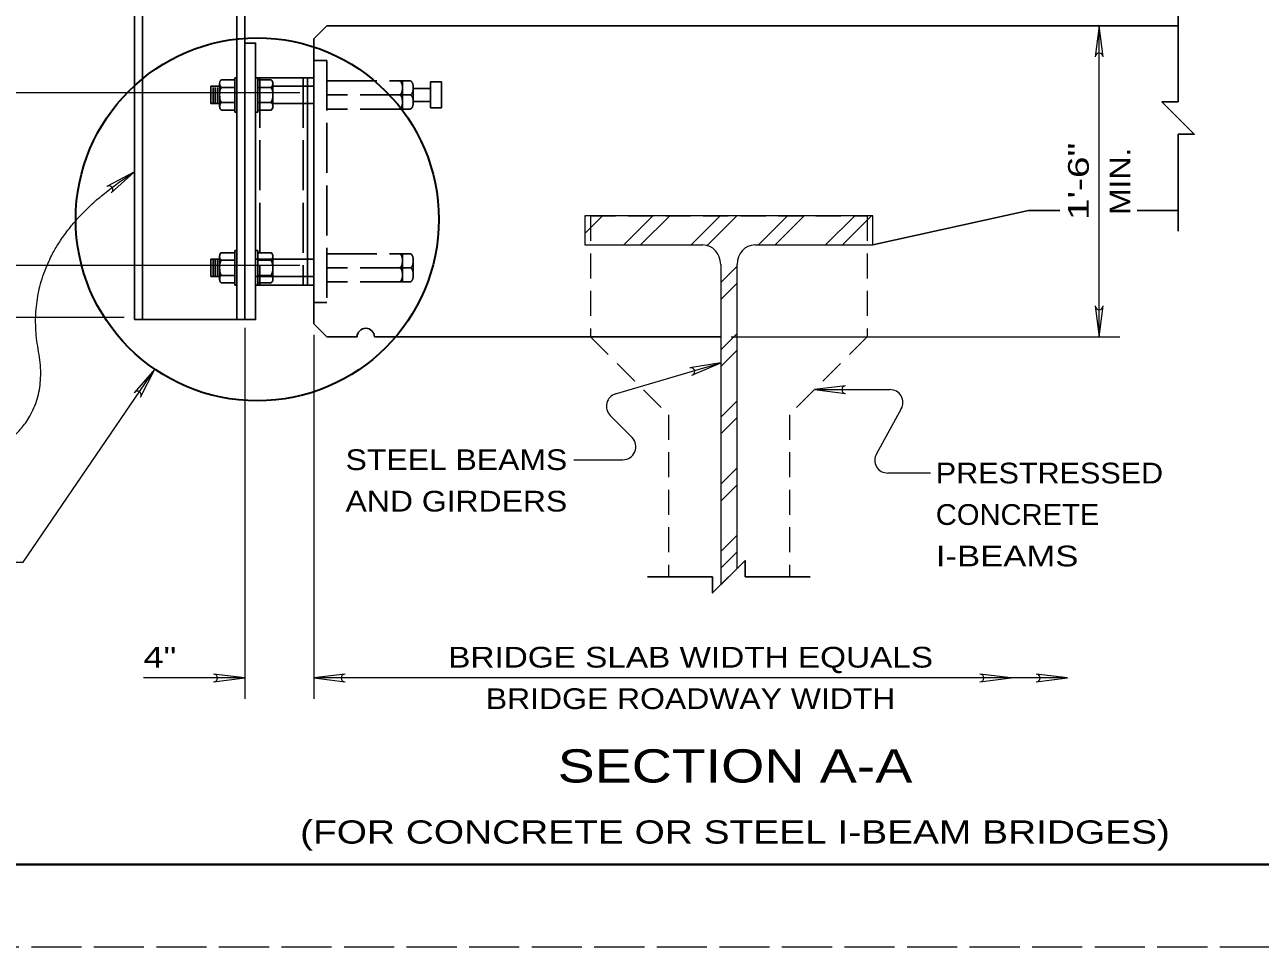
# Model space of a CAD drawing. Extents: x 1285 to 1427, y 1365 to 1427.
# Drawn here: x 1405.11 to 1415.03, y 1397.33 to 1404.75 of the extents above; entities that cross this region are included whole.
import ezdxf
from ezdxf.enums import TextEntityAlignment as Align

# ---------------------------------------------------------------- set-up
doc = ezdxf.new("R2010")
doc.units = 0
doc.header["$LTSCALE"] = 0.067
doc.linetypes.add('LONG_DASHED', pattern=[7.5, 6, -1.5])
doc.linetypes.add('MEDIUM_DASHED', pattern=[4.5, 3, -1.5])
for name, color, linetype, lineweight in [('1', 7, 'Continuous', 40), ('42', 7, 'Continuous', 25), ('43', 7, 'Continuous', 25), ('44', 7, 'Continuous', 13)]:
    doc.layers.add(name, color=color, linetype=linetype, lineweight=lineweight)

msp = doc.modelspace()

# ---------------------------------------------------------------- linework, layer by layer
at = {"layer": '1', "linetype": 'LONG_DASHED', "lineweight": 13}
msp.add_lwpolyline([(1381.33333, 1426.66667), (1426.66667, 1426.66667), (1426.66667, 1397.33333), (1381.33333, 1397.33333)], close=True, dxfattribs=at)
at = {"layer": '1'}
msp.add_lwpolyline([(1384, 1426), (1426, 1426), (1426, 1398), (1384, 1398)], close=True, dxfattribs=at)
at = {"layer": '42'}
for p, q in [((1405.98811, 1409.04422), (1405.98811, 1402.37744)), ((1406.05133, 1409.04422), (1406.05133, 1402.37744)), ((1406.811, 1409.04422), (1406.811, 1402.37744)), ((1414.37189, 1404.90533), (1414.37189, 1404.12733)), ((1407.42967, 1404.63444), (1407.53389, 1404.73867)), ((1407.53389, 1404.73867), (1414.37189, 1404.73867)), ((1407.42967, 1404.63444), (1407.42967, 1402.34289)), ((1406.67222, 1404.09178), (1406.67222, 1404.27411)), ((1406.68956, 1404.30444), (1406.79378, 1404.30444)), ((1406.79378, 1404.32178), (1406.79367, 1404.04411)), ((1406.79378, 1404.32178), (1406.811, 1404.32178)), ((1407.42978, 1404.32189), (1406.96111, 1404.32189)), ((1406.97833, 1404.32178), (1406.96111, 1404.32178)), ((1406.97833, 1404.32178), (1406.97844, 1404.04411)), ((1407.08256, 1404.30444), (1406.97833, 1404.30444)), ((1407.09989, 1404.09178), (1407.09989, 1404.27411)), ((1407.37778, 1404.25233), (1407.37778, 1404.32189)), ((1406.62011, 1404.24367), (1406.62011, 1404.12211)), ((1406.63744, 1404.24367), (1406.63744, 1404.12211)), ((1406.65478, 1404.24367), (1406.65478, 1404.12211)), ((1406.79367, 1404.24367), (1406.68956, 1404.24367)), ((1406.97844, 1404.24367), (1407.08256, 1404.24367)), ((1407.09989, 1404.25233), (1407.42978, 1404.25233)), ((1406.79367, 1404.12211), (1406.68956, 1404.12211)), ((1406.97844, 1404.12211), (1407.08256, 1404.12211)), ((1407.09989, 1404.11344), (1407.42967, 1404.11344)), ((1407.37778, 1402.86344), (1407.37778, 1404.11344)), ((1406.79367, 1404.06144), (1406.68956, 1404.06144)), ((1406.79367, 1404.04411), (1406.811, 1404.04411)), ((1406.97844, 1404.04411), (1406.96111, 1404.04411)), ((1406.97844, 1404.06144), (1407.08256, 1404.06144)), ((1414.37189, 1403.86678), (1414.37189, 1403.08867)), ((1411.91956, 1402.97756), (1413.16956, 1403.25533)), ((1413.16956, 1403.25533), (1413.42056, 1403.25533)), ((1414.04189, 1403.25533), (1414.37189, 1403.25533)), ((1406.67222, 1402.70289), (1406.67222, 1402.88522)), ((1406.68956, 1402.91556), (1406.79378, 1402.91556)), ((1406.79378, 1402.93289), (1406.79367, 1402.65522)), ((1406.79378, 1402.93289), (1406.811, 1402.93289)), ((1406.97833, 1402.93289), (1406.96111, 1402.93289)), ((1406.97833, 1402.93289), (1406.97844, 1402.65522)), ((1407.08256, 1402.91556), (1406.97833, 1402.91556)), ((1407.09989, 1402.70289), (1407.09989, 1402.88522)), ((1406.62011, 1402.85478), (1406.62011, 1402.73322)), ((1406.63744, 1402.85478), (1406.63744, 1402.73322)), ((1406.65478, 1402.85478), (1406.65478, 1402.73322)), ((1406.79367, 1402.85478), (1406.68956, 1402.85478)), ((1406.97844, 1402.85478), (1407.08256, 1402.85478)), ((1407.09989, 1402.86344), (1407.42967, 1402.86344)), ((1406.79367, 1402.73322), (1406.68956, 1402.73322)), ((1406.97844, 1402.73322), (1407.08256, 1402.73322)), ((1407.09989, 1402.72456), (1407.42967, 1402.72456)), ((1407.37778, 1402.65522), (1407.37778, 1402.72456)), ((1406.79367, 1402.67256), (1406.68956, 1402.67256)), ((1406.79367, 1402.65522), (1406.811, 1402.65522)), ((1406.97844, 1402.65522), (1406.96111, 1402.65522)), ((1406.97844, 1402.67256), (1407.08256, 1402.67256)), ((1407.42967, 1402.34289), (1407.53389, 1402.23867)), ((1407.53389, 1402.23867), (1407.77689, 1402.23867)), ((1407.91578, 1402.23867), (1410.69733, 1402.23867)), ((1410.11022, 1400.31133), (1410.63267, 1400.31133)), ((1410.89322, 1400.31133), (1411.41578, 1400.31133))]:
    msp.add_line(p, q, dxfattribs=at)
at = {"layer": '42', "linetype": 'LONG_DASHED'}
for p, q in [((1406.99589, 1404.32189), (1406.99589, 1402.65522)), ((1407.343, 1404.32189), (1407.343, 1402.65522)), ((1407.53378, 1404.29589), (1408.20222, 1404.29589)), ((1408.14144, 1404.29589), (1408.14144, 1404.23522)), ((1408.45389, 1404.28733), (1408.36711, 1404.28733)), ((1408.36711, 1404.28733), (1408.36711, 1404.079)), ((1407.37778, 1404.25233), (1407.37778, 1404.11344)), ((1408.20222, 1404.183), (1407.53378, 1404.183)), ((1408.22822, 1404.23522), (1408.36711, 1404.23522)), ((1408.22822, 1404.23522), (1408.22822, 1404.15211)), ((1408.22822, 1404.131), (1408.36711, 1404.131)), ((1408.20222, 1404.07011), (1407.53378, 1404.07011)), ((1407.53378, 1402.907), (1408.20222, 1402.907)), ((1408.14144, 1402.907), (1408.14144, 1402.84633)), ((1406.96111, 1402.86344), (1407.09989, 1402.86344)), ((1407.37778, 1402.86344), (1407.37778, 1402.72456)), ((1408.20222, 1402.79411), (1407.53378, 1402.79411)), ((1408.22822, 1402.84633), (1408.22822, 1402.76322)), ((1406.96111, 1402.72456), (1407.09989, 1402.72456)), ((1408.20222, 1402.68122), (1407.53378, 1402.68122))]:
    msp.add_line(p, q, dxfattribs=at)
at = {"layer": '42', "lineweight": 13}
for p, q in [((1409.60644, 1403.20456), (1409.61278, 1403.21089)), ((1409.60644, 1403.07), (1409.74733, 1403.21089)), ((1409.91967, 1402.97756), (1410.153, 1403.21089)), ((1410.05422, 1402.97756), (1410.28756, 1403.21089)), ((1410.45989, 1402.97756), (1410.69322, 1403.21089)), ((1410.58656, 1402.96967), (1410.82778, 1403.21089)), ((1411.00011, 1402.97756), (1411.23344, 1403.21089)), ((1411.13467, 1402.97756), (1411.368, 1403.21089)), ((1411.54033, 1402.97756), (1411.77367, 1403.21089)), ((1411.67489, 1402.97756), (1411.90822, 1403.21089)), ((1409.60644, 1402.97756), (1410.55456, 1402.97756)), ((1410.69733, 1402.67478), (1410.82867, 1402.80611)), ((1410.69733, 1402.54022), (1410.82867, 1402.67156)), ((1410.69733, 1402.13456), (1410.82867, 1402.26589)), ((1410.69733, 1402), (1410.82867, 1402.13133)), ((1410.69733, 1401.59433), (1410.82867, 1401.72567)), ((1410.69733, 1401.45978), (1410.82867, 1401.59111)), ((1410.69733, 1401.05411), (1410.82867, 1401.18544)), ((1410.69733, 1400.91956), (1410.82867, 1401.05089)), ((1410.69733, 1400.51389), (1410.82867, 1400.64522)), ((1410.69733, 1400.37933), (1410.82867, 1400.51067))]:
    msp.add_line(p, q, dxfattribs=at)
at = {"layer": '42'}
for points in [[(1406.87422, 1409.04422), (1406.87422, 1402.37744), (1405.98811, 1402.37744)], [(1406.96111, 1404.32189), (1406.96111, 1402.65522), (1407.42967, 1402.65522)], [(1406.67222, 1404.25233), (1406.60278, 1404.25233), (1406.60278, 1404.11344), (1406.67222, 1404.11344)], [(1414.37189, 1404.12733), (1414.24167, 1404.12733), (1414.502, 1403.86678), (1414.37189, 1403.86678)], [(1406.67222, 1402.86344), (1406.60278, 1402.86344), (1406.60278, 1402.72456), (1406.67222, 1402.72456)], [(1410.63267, 1400.31144), (1410.63267, 1400.18122), (1410.89322, 1400.44156), (1410.89322, 1400.31144)]]:
    msp.add_lwpolyline(points, dxfattribs=at)
msp.add_lwpolyline([(1406.87422, 1404.59967), (1406.96111, 1404.59967), (1406.96111, 1402.37744), (1406.87422, 1402.37744)], close=True, dxfattribs=at)
at = {"layer": '42', "linetype": 'LONG_DASHED'}
msp.add_lwpolyline([(1407.42967, 1404.46078), (1407.53378, 1404.46078), (1407.53378, 1402.51633), (1407.42967, 1402.51633)], close=True, dxfattribs=at)
for points in [[(1408.45389, 1404.28733), (1408.45389, 1404.079), (1408.36711, 1404.079)], [(1408.14144, 1404.23522), (1408.14144, 1404.131), (1408.14144, 1404.07011)], [(1408.14144, 1402.84633), (1408.14144, 1402.74211), (1408.14144, 1402.68122)]]:
    msp.add_lwpolyline(points, dxfattribs=at)
at = {"layer": '42', "lineweight": 13}
for points in [[(1410.97122, 1402.97756), (1411.91956, 1402.97756), (1411.91956, 1403.21089), (1409.60644, 1403.21089), (1409.60644, 1402.97756)], [(1410.69733, 1402.82022), (1410.69733, 1400.24589), (1410.82867, 1400.377), (1410.82867, 1402.82022)]]:
    msp.add_lwpolyline(points, dxfattribs=at)
at = {"layer": '42'}
msp.add_arc((1407.84633, 1402.23867), 0.06944, 0, 180, dxfattribs=at)
for centre, major_axis, ratio, start_param, end_param in [((1406.68956, 1404.27411), (0, -0.03033), 0.571429, 3.1415927, 6.2831853), ((1407.08256, 1404.27411), (0, -0.03033), 0.571429, 6.2831853, 9.424778), ((1406.68956, 1404.18289), (0, 0.06078), 0.285192, 6.2831853, 9.424778), ((1407.08256, 1404.18289), (0, 0.06078), 0.285192, 3.1415927, 6.2831853), ((1406.68956, 1404.09178), (0, 0.03033), 0.571429, 6.2831853, 9.424778), ((1407.08256, 1404.09178), (0, 0.03033), 0.571429, 3.1415927, 6.2831853), ((1406.68956, 1402.88522), (0, -0.03033), 0.571429, 3.1415927, 6.2831853), ((1407.08256, 1402.88522), (0, -0.03033), 0.571429, 6.2831853, 9.424778), ((1406.68956, 1402.794), (0, 0.06078), 0.285192, 6.2831853, 9.424778), ((1407.08256, 1402.794), (0, 0.06078), 0.285192, 3.1415927, 6.2831853), ((1406.68956, 1402.70289), (0, 0.03033), 0.571429, 6.2831853, 9.424778), ((1407.08256, 1402.70289), (0, 0.03033), 0.571429, 3.1415927, 6.2831853)]:
    msp.add_ellipse(centre, major_axis=major_axis, ratio=ratio, start_param=start_param, end_param=end_param, dxfattribs=at)
at = {"layer": '42', "linetype": 'LONG_DASHED'}
for centre, start_param, end_param in [((1408.11539, 1404.23947), 1.4944301, 3.1415927), ((1408.20224, 1404.23947), 1.4944301, 3.1415927), ((1408.11539, 1404.23947), 6.2831853, 7.7776154), ((1408.11539, 1404.1266), 1.6488082, 3.1415927), ((1408.20224, 1404.23947), 6.2831853, 7.7776154), ((1408.20224, 1404.1266), 1.6488082, 3.1415927), ((1408.11539, 1404.1266), 6.2831853, 7.9319935), ((1408.20224, 1404.1266), 6.2831853, 7.9319935), ((1408.11539, 1402.85058), 1.4944301, 3.1415927), ((1408.20224, 1402.85058), 1.4944301, 3.1415927), ((1408.11539, 1402.85058), 6.2831853, 7.7776154), ((1408.11539, 1402.73771), 1.6488082, 3.1415927), ((1408.20224, 1402.85058), 6.2831853, 7.7776154), ((1408.20224, 1402.73771), 1.6488082, 3.1415927), ((1408.11539, 1402.73771), 6.2831853, 7.9319935), ((1408.20224, 1402.73771), 6.2831853, 7.9319935)]:
    msp.add_ellipse(centre, major_axis=(0, -0.05644), ratio=0.461034, start_param=start_param, end_param=end_param, dxfattribs=at)
at = {"layer": '42', "lineweight": 13}
for centre, start_param, end_param in [((1410.5546, 1402.82019), 4.712389, 6.2831853), ((1410.97141, 1402.82019), 6.2831853, 7.8539816)]:
    msp.add_ellipse(centre, major_axis=(0, 0.15736), ratio=0.907326, start_param=start_param, end_param=end_param, dxfattribs=at)
at = {"layer": '43', "linetype": 'MEDIUM_DASHED', "lineweight": 13}
for points in [[(1409.65189, 1403.21089), (1411.87411, 1403.21089), (1411.87411, 1402.23867), (1411.24911, 1401.61367), (1411.24911, 1400.31133)], [(1409.65189, 1403.21089), (1409.65189, 1402.23867), (1410.27689, 1401.61367), (1410.27689, 1400.31133)]]:
    msp.add_lwpolyline(points, dxfattribs=at)
at = {"layer": '44'}
for p, q in [((1413.769, 1404.48867), (1413.73778, 1404.73867)), ((1407.31644, 1404.20089), (1403.908, 1404.20089)), ((1405.988, 1403.56456), (1405.76556, 1403.44611)), ((1405.80156, 1403.39511), (1405.988, 1403.56456)), ((1407.31644, 1402.812), (1403.908, 1402.812)), ((1413.70656, 1402.48867), (1413.73778, 1402.23867)), ((1413.73778, 1402.23867), (1413.769, 1402.48867)), ((1405.90467, 1402.39533), (1402.908, 1402.39533)), ((1406.87422, 1402.312), (1406.87422, 1399.33122)), ((1407.42956, 1402.25633), (1407.42956, 1399.33122)), ((1410.78067, 1402.23867), (1413.90444, 1402.23867)), ((1409.85356, 1401.781), (1410.69733, 1402.03122)), ((1410.69733, 1402.03122), (1410.44878, 1401.99011)), ((1410.46656, 1401.93022), (1410.69733, 1402.03122)), ((1406.03722, 1401.75456), (1406.15233, 1401.97867)), ((1411.70067, 1401.84644), (1411.45067, 1401.81522)), ((1411.45067, 1401.81522), (1412.05711, 1401.81522)), ((1411.45067, 1401.81522), (1411.70067, 1401.784)), ((1409.98589, 1401.42922), (1409.80911, 1401.60789)), ((1412.14822, 1401.66067), (1411.94822, 1401.299)), ((1409.51789, 1401.25178), (1409.91189, 1401.25178)), ((1412.38378, 1401.14444), (1412.03933, 1401.14444)), ((1406.87422, 1399.49789), (1406.62422, 1399.52911)), ((1407.67956, 1399.52911), (1407.42956, 1399.49789)), ((1413.03, 1399.49789), (1412.78, 1399.52911)), ((1413.482, 1399.49789), (1413.232, 1399.52911)), ((1406.87422, 1399.49789), (1406.06067, 1399.49789)), ((1406.62422, 1399.46667), (1406.87422, 1399.49789)), ((1413.482, 1399.49789), (1407.42956, 1399.49789)), ((1407.42956, 1399.49789), (1407.67956, 1399.46667)), ((1412.78, 1399.46667), (1413.03, 1399.49789)), ((1413.232, 1399.46667), (1413.482, 1399.49789))]:
    msp.add_line(p, q, dxfattribs=at)
for points in [[(1413.73778, 1402.23867), (1413.73778, 1404.73867), (1413.70656, 1404.48867)], [(1404.616, 1400.42956), (1405.09489, 1400.42956), (1406.15233, 1401.97867), (1405.98556, 1401.78978)]]:
    msp.add_lwpolyline(points, dxfattribs=at)
at = {"layer": '44', "lineweight": 35}
msp.add_circle((1406.97456, 1403.18311), 1.45833, dxfattribs=at)
at = {"layer": '44'}
for centre, radius, start, end in [((1413.73778, 1404.48867), 0.03122, 0, 180), ((1405.78356, 1403.42067), 0.03122, 305.13789, 125.13789), ((1413.73778, 1402.48867), 0.03122, 180, 0), ((1410.45765, 1401.96014), 0.03122, 286.51772, 106.51772), ((1406.01139, 1401.77219), 0.03122, 325.68202, 145.68202), ((1411.70067, 1401.81522), 0.03122, 90, 270), ((1412.05711, 1401.71106), 0.10417, 331.05021, 90), ((1409.88318, 1401.68115), 0.10417, 106.51701, 224.69304), ((1409.91186, 1401.35594), 0.10417, 270, 44.69318), ((1412.03935, 1401.24861), 0.10417, 151.04716, 270), ((1406.62422, 1399.49789), 0.03122, 270, 90), ((1407.67956, 1399.49789), 0.03122, 90, 270), ((1412.78, 1399.49789), 0.03122, 270, 90), ((1413.232, 1399.49789), 0.03122, 270, 90)]:
    msp.add_arc(centre, radius, start, end, dxfattribs=at)
msp.add_open_spline([(1404.07467, 1401.08189), (1405.37744, 1401.27011), (1405.058, 1402.97078), (1405.988, 1403.56456)], degree=2, dxfattribs=at)

# ---------------------------------------------------------------- texts
for s, width, p in [('1\'-6"', 1.4, (1413.65444, 1403.48872)), ('MIN.', 1.15, (1413.98778, 1403.48867))]:
    msp.add_text(s, height=0.1667, rotation=90, dxfattribs=dict(at, width=width)).set_placement(p, align=Align.CENTER)
for s, width, p in [('STEEL BEAMS', 1.15, (1407.684, 1401.16844)), ('PRESTRESSED', 1.1, (1412.42544, 1401.06111)), ('AND GIRDERS', 1.15, (1407.684, 1400.83511)), ('CONCRETE', 1.05, (1412.42544, 1400.72778)), ('I-BEAMS', 1.25, (1412.42544, 1400.39444)), ('4"', 1.3, (1406.06067, 1399.58122))]:
    msp.add_text(s, height=0.1667, dxfattribs=dict(at, width=width)).set_placement(p)
for s, height, width, p in [('BRIDGE SLAB WIDTH EQUALS', 0.1667, 1.2, (1410.45578, 1399.58122)), ('BRIDGE ROADWAY WIDTH', 0.1667, 1.15, (1410.45578, 1399.24789)), ('SECTION A-A', 0.2667, 1.25, (1410.81228, 1398.65767)), ('(FOR CONCRETE OR STEEL I-BEAM BRIDGES)', 0.1867, 1.25, (1410.81222, 1398.16656))]:
    msp.add_text(s, height=height, dxfattribs=dict(at, width=width)).set_placement(p, align=Align.CENTER)

doc.saveas('drawing.dxf')
